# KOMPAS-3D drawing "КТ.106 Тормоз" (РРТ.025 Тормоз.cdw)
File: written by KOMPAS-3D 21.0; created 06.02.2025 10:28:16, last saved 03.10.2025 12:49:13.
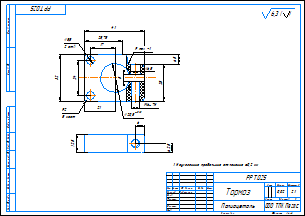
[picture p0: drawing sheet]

Sheet 1: A4x2, landscape

Document properties: Автор: User; Знак неуказанной шероховатости: 4; Параметр неуказанной шероховатости: 6,3; Масса: 0.02108; Форматы листов документа: A4@4~2; Полное имя файла: ..\Модели КД\РРТ.25 Тормоз.m3d; Организация: User

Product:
- Part/product: КТ.106 Тормоз
    Материал: Фторопласт-4  ГОСТ 10007-80 Е (density 2200 kg/m3)
    Масса: 0.02108
    Комментарий: User
  - Body: Тело 1
      Масса: 0.020559
  - Body: Тело 2
      Масса: 0.020559

Title block, sheet 1: Наименование: Тормоз; designation: РРТ.025; Материал: Полиацеталь; Масса: 0,02; Количество листов документа: 1; organisation: ООО ТПК Пегас; Форматы листов документа: A4 2; stored path: D:\Marat\work\eholot\KazanTarget\Новые проекты\КТ Pro\детали\Тормоз\Тормоз.cdw; Разработал: Набиуллин

Views: Проекционный вид 2, Местный разрез 1, Проекционный вид 3
Referenced files in C:\Users\User\Desktop\Ручной ротатор КД\Модели КД\: РРТ.25 Тормоз.m3d
Referenced files in D:\Marat\work\eholot\KazanTarget\Новые проекты\КТ Pro\детали\Тормоз\: тормоз.m3d
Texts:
  max =1
  КТ.106 Тормоз
Dimensions and other numbers on the sheet: -7Н; 6; 5; 25; 5,5; 2 отв; 2; 5 мест; 32; 17; 24; 41; 25,75; 21; 20,5; 6,5; 6,25; 12,5; 6,3; 2:1; 1; 0,02

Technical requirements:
  Неуказанные предельные отклонения  0,2 мм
